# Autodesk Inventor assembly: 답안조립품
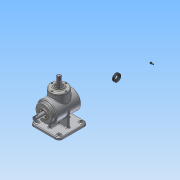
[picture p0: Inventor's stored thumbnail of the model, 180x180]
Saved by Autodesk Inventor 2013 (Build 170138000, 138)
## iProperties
Created: 2015-07
Part Number: 답안조립품
Document SubType Name: Assembly
Designer: Administrator
Author: Administrator
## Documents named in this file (14)
- C:\Users\Administrator\Desktop\450706V1021\답안조립품.iam
- C:\Users\Administrator\Desktop\450706V1021\M4.ipt
- C:\Users\Administrator\Desktop\450706V1021\메인 베벨기어.ipt
- C:\Users\Administrator\Desktop\450706V1021\메인 축.ipt
- 메인 축.ipt
- C:\Users\Administrator\Desktop\450706V1021\베어링 6203.ipt
- C:\Users\Administrator\Desktop\450706V1021\본체.ipt
- C:\Users\Administrator\Desktop\450706V1021\서브 베벨기어.ipt
- C:\Users\Administrator\Desktop\450706V1021\서브 축.ipt
- 서브 축.ipt
- C:\Users\Administrator\Desktop\450706V1021\오일실.ipt
- C:\Users\Administrator\Desktop\450706V1021\커버.ipt
- C:\Users\Administrator\Desktop\450706V1021\키 4x4.ipt
- C:\Users\Administrator\Desktop\450706V1021\키 5x5.ipt
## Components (1 placed, 1 different names)
1. M4:1
